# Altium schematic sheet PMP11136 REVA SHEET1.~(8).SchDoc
size 431 x 279 mm; Date: Not shown in title block; ApprovedBy: Not shown in title block; CheckedBy: Not shown in title block; Author: Not shown in title block; CompanyName: Not shown in title block; Engineer: Not shown in title block; Organization: Not shown in title block; Address1: Not shown in title block; Address2: Not shown in title block; Address3: Not shown in title block; Address4: Not shown in title block; DocumentNumber: 1; Revision: Use project parameter SCH_Rev; SheetNumber: 1; SheetTotal: 3; PageSetup: Record=PageOptions¦CenterHorizontal=True¦CenterVertical=True¦PrintScale=1.00¦XCorrection=1.00¦YCorrection=1.00¦PrintKind=0¦BorderSize=5000000¦LeftOffset=0¦BottomOffset=0¦Orientation=2¦PaperLength=1000¦PaperWidth=1000¦Scale=100¦PaperSource=15¦PrintQuality=600¦MediaType=1¦DitherType=10¦PaperKind=Letter¦PrintScaleMode=1
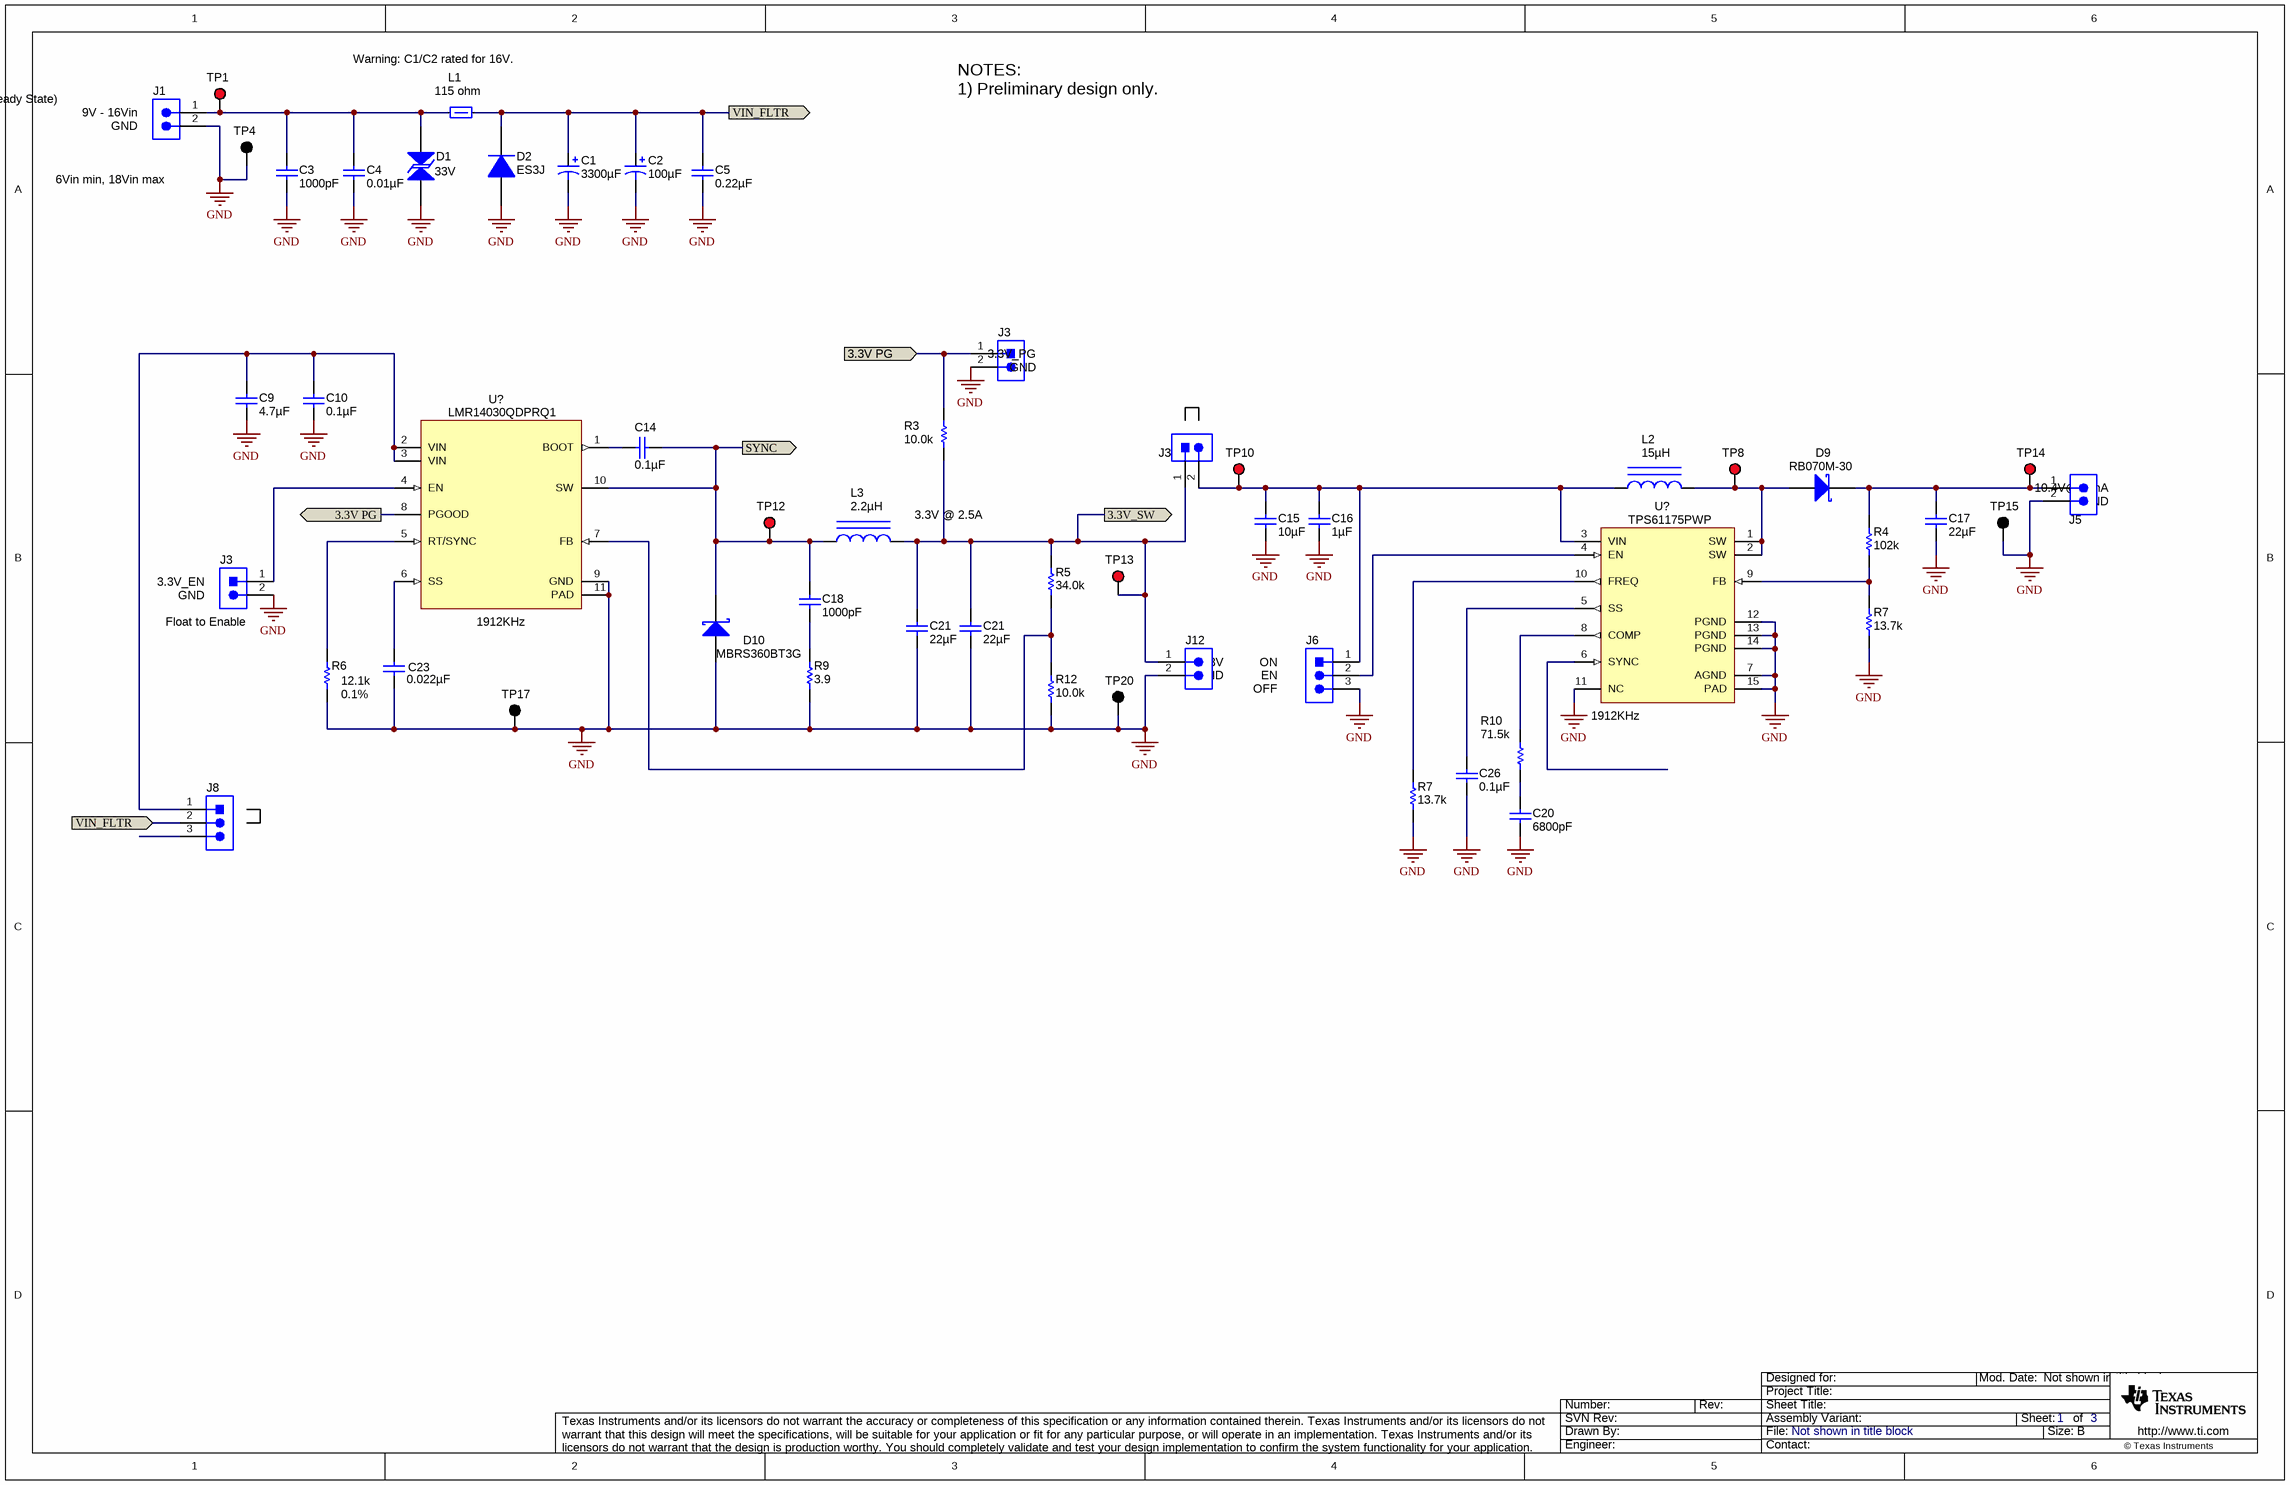
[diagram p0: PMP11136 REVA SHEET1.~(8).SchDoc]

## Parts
(Parts that share a designator on the sheet are numbered #1, #2 ... from top to bottom, then left to right.)
C1  ValueDisplayed: 3300µF  [SM_RADIAL_J16]  (hidden comment: EEV-FK1C332M)
C2  ValueDisplayed: 100µF  [SM_RADIAL_D]  (hidden comment: EEE-FK1C101P)
C3  ValueDisplayed: 1000pF  [0603]  (hidden comment: C1608C0G2A102J)
C4  ValueDisplayed: 0.01µF  [0603]  (hidden comment: C1608X7R2A103K)
C5  ValueDisplayed: 0.22µF  [0603]  (hidden comment: C1608X7R1H224K080AB)
C9  ValueDisplayed: 4.7µF  [1210]  (hidden comment: C3225X7R1H475M250AB)
C10  ValueDisplayed: 0.1µF  [0603]  (hidden comment: C1608X7R1H104K)
C14  ValueDisplayed: 0.1µF  [0603]  (hidden comment: C1608X7R1H104K)
C15  ValueDisplayed: 10µF  [0805]  (hidden comment: GRM21BR71A106KE51L)
C16  ValueDisplayed: 1µF  [0603]  (hidden comment: C1608X7R1E105K)
C17  ValueDisplayed: 22µF  [1210]  (hidden comment: C3225X7R1A226M230AC)
C18  ValueDisplayed: 1000pF  [0603]  (hidden comment: C1608C0G2A102J)
C20  ValueDisplayed: 6800pF  [0603]  (hidden comment: C1608C0G1E682J)
C21#1  ValueDisplayed: 22µF  [1210]  (hidden comment: C3225X7R1C226M250AC)
C21#2  ValueDisplayed: 22µF  [1210]  (hidden comment: C3225X7R1C226M250AC)
C23  ValueDisplayed: 0.022µF  [0603]  (hidden comment: C1608X7R1H223K)
C26  ValueDisplayed: 0.1µF  [0603]  (hidden comment: C1608X7R1H104K)
D1  value 33V  [DO-214AB-Bi]  (hidden comment: 1.5SMC33CA-E3/57T)
D2  ES3J  [SMC]
D9  RB070M-30  [SOD-123]
D10  MBRS360BT3G  [SMB]
J1  ED555/2DS  [TERM_BLK_ED555-2DS]  (value not drawn)
J3#1  PEC02SAAN  [CONN_PEC02SAAN]  (value not drawn)
J3#2  PEC02SAAN  [CONN_PEC02SAAN]  (value not drawn)
J3#3  PEC02SAAN  [CONN_PEC02SAAN]  (value not drawn)
J5  ED555/2DS  [TERM_BLK_ED555-2DS]  (value not drawn)
J6  PEC03SAAN  [CONN_PEC03SAAN]  (value not drawn)
J8  PEC03SAAN  [CONN_PEC03SAAN]  (value not drawn)
J12  ED555/2DS  [TERM_BLK_ED555-2DS]  (value not drawn)
L1  value 115 ohm  [28F0181]  (hidden comment: 28F0181-1SR-10)
L2  ValueDisplayed: 15µH  [IND_VLF403215]  (hidden comment: VLF403215MT- 150M)
L3  ValueDisplayed: 2.2µH  [SDR7045]  (hidden comment: SLF6045T-2R2N3R3-3PF)
R3  ValueDisplayed: 10.0k  [0603]  (hidden comment: CRCW060310K0FKEA)
R4  ValueDisplayed: 102k  [0603]  (hidden comment: CRCW0603102KFKEA)
R5  ValueDisplayed: 34.0k  [0603]  (hidden comment: CRCW060334K0FKEA)
R6  Value1: 0.1%  ValueDisplayed: 12.1k  [0603]
R7#1  ValueDisplayed: 13.7k  [0603]  (hidden comment: CRCW060313K7FKEA)
R7#2  ValueDisplayed: 13.7k  [0603]  (hidden comment: CRCW060313K7FKEA)
R9  value 3.9  [2010]  (hidden comment: CRCW20103R90JNEF)
R10  ValueDisplayed: 71.5k  [0603]  (hidden comment: CRCW060371K5FKEA)
R12  ValueDisplayed: 10.0k  [0603]  (hidden comment: CRCW060310K0FKEA)
TP1  5000  [Keystone5000]  (value not drawn)
TP4  5001  [Keystone5001]  (value not drawn)
TP8  5000  [Keystone5000]  (value not drawn)
TP10  5000  [Keystone5000]  (value not drawn)
TP12  5000  [Keystone5000]  (value not drawn)
TP13  5000  [Keystone5000]  (value not drawn)
TP14  5000  [Keystone5000]  (value not drawn)
TP15  5001  [Keystone5001]  (value not drawn)
TP17  5001  [Keystone5001]  (value not drawn)
TP20  5001  [Keystone5001]  (value not drawn)
U?#1  LMR14030QDPRQ1  [DPR0010A]
U?#2  TPS61175PWP  [PWP0014E_N]

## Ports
3.3V PG, 3.3V_SW, SYNC, VIN_FLTR

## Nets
GND: C1.2(-) C2.2(-) C3.2 C4.2 C5.2 C9.1 C10.2 C15.2 C16.2 C17.2 C20.2 C21#1.2 C21#2.2 C23.2 C26.2 D1.1 D2.2(A) D10.2(A) J1.2 J3#1.2 J3#3.2 J5.2 J6.3 J12.2 R6.1 R7#1.1 R7#2.1 R9.1 R12.1 TP4.1 TP15.1 TP17.1 TP20.1 U?#1.9(GND) U?#1.11(PAD) U?#2.7(AGND) U?#2.11(NC) U?#2.12(PGND) U?#2.13(PGND) U?#2.14(PGND) U?#2.15(PAD)
3.3V PG: J3#1.1 R3.2 U?#1.8(PGOOD) ; port 3.3V PG
3.3V_SW: C21#1.1 C21#2.1 J3#2.1 J12.1 L3.2 R3.1 R5.2 TP13.1 ; port 3.3V_SW
SYNC: C14.2 C18.1 D10.1(K) L3.1 TP12.1 U?#1.10(SW) ; port SYNC
VIN_FLTR: C1.1(+) C2.1(+) C5.1 D2.1(K) J8.2 L1.2 ; port VIN_FLTR
NetC3_1: C3.1 C4.1 D1.2 J1.1 L1.1 TP1.1
NetC9_2: C9.2 C10.1 J8.1 U?#1.2(VIN) U?#1.3(VIN)
NetC14_1: C14.1 U?#1.1(BOOT)
NetC15_1: C15.1 C16.1 J3#2.2 J6.1 L2.1 TP10.1 U?#2.3(VIN)
NetC17_1: C17.1 D9.1(K) J5.1 R4.2 TP14.1
NetC18_2: C18.2 R9.2
NetC20_1: C20.1 R10.1
NetC23_1: C23.1 U?#1.6(SS)
NetC26_1: C26.1 U?#2.5(SS)
NetD9_2: D9.2(A) L2.2 TP8.1 U?#2.1(SW) U?#2.2(SW)
NetJ3#3_1: J3#3.1 U?#1.4(EN)
NetJ6_2: J6.2 U?#2.4(EN)
NetR4_1: R4.1 R7#1.2 U?#2.9(FB)
NetR5_1: R5.1 R12.2 U?#1.7(FB)
NetR6_2: R6.2 U?#1.5(RT/SYNC)
NetR7#2_2: R7#2.2 U?#2.10(FREQ)
NetR10_2: R10.2 U?#2.8(COMP)

Not connected (* = marked no-connect by the designer): J8 3; U?#2 6(SYNC)

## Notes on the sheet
- (near J1) (Steady State)
- Warning: C1/C2 rated for 16V.
- (near J1) 9V - 16Vin
- (near J1) GND
- NOTES:
  1) Preliminary design only.
- (near J1) 6Vin min, 18Vin max
- (near J3#1) 3.3V_PG
- (near J3#1) GND
- (near J5) 10.4V@30mA
- (near J5) GND
- 3.3V @ 2.5A
- (near J3#3) 3.3V_EN
- (near J3#3) GND
- (near J3#3) Float to Enable
- (near U?#1) 1912KHz
- (near J12) 3.3V
- (near J12) GND
- (near J6) ON
- (near J6) EN
- (near J6) OFF
- (near U?#2) 1912KHz

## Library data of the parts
C1 = EEV-FK1C332M: CAP, AL, 3300 µF, 16 V, +/- 20%, 0.035 ohm, SMD; Manufacturer: Panasonic; Polarized: Y; CompType: Capacitor; Value: 3300uF; U/M: EA; Cap_F: 0.0033; Tolerance_%: 20; VDC_V: 16; Value2: 16V; ESR_ohm: 0.035; IRMS_A: 1.8; TaMin_C: -55; TaMax_C: 105; Cap_Case: J16
C2 = EEE-FK1C101P: CAP, AL, 100 µF, 16 V, +/- 20%, 0.36 ohm, SMD; Manufacturer: Panasonic; Polarized: Y; CompType: Capacitor; Value: 100uF; U/M: EA; Cap_F: 0.0001; Tolerance_%: 20; VDC_V: 16; Value2: 16V; ESR_ohm: 0.36; IRMS_A: 0.24; TaMin_C: -55; TaMax_C: 105; Cap_Case: D
C3 C18 = C1608C0G2A102J: CAP, CERM, 1000 pF, 100 V, +/- 5%, C0G/NP0, 0603; Manufacturer: TDK; Polarized: N; CompType: Capacitor; Value: 1000pF; U/M: EA; Cap_F: 0.000000001; Tolerance_%: 5; ESR_ohm: 0.0589; Value1: 0.0589 ohm; VDC_V: 100; Value2: 100V; TaMin_C: -55; TaMax_C: 125
C4 = C1608X7R2A103K: CAP, CERM, 0.01 µF, 100 V, +/- 10%, X7R, 0603; Manufacturer: TDK; Polarized: N; CompType: Capacitor; Value: 0.01uF; U/M: EA; Cap_F: 0.00000001; Tolerance_%: 10; ESR_ohm: 0.0661; Value1: 0.0661 ohm; VDC_V: 100; Value2: 100V; TaMin_C: -55; TaMax_C: 125
C5 = C1608X7R1H224K080AB: CAP, CERM, 0.22 µF, 50 V, +/- 10%, X7R, 0603; Manufacturer: TDK; Polarized: N; CompType: Capacitor; Value: 0.22uF; U/M: EA; Cap_F: 0.00000022; Tolerance_%: 10; Value1: Unknown; VDC_V: 50; Value2: 50V; TaMin_C: -55; TaMax_C: 125
C9 = C3225X7R1E106M: CAP, CERM, 4.7uF, 50V, +/-20%, X7R, 1210; Manufacturer: TDK; Polarized: N; CompType: Capacitor; U/M: EA; Cap_F: 0.00001; Tolerance_%: 20; ESR_Ohm: 0.0027; Value1: 0.0027 ohm; VDC_V: 50; IRMS_A: 3; TaMin_C: -55; TaMax_C: 125
C10 C14 C26 = C1608X7R1H104K: CAP, CERM, 0.1uF, 50V, +/-10%, X7R, 0603; Manufacturer: TDK; Polarized: N; CompType: Capacitor; U/M: EA; Cap_F: 0.0000001; Tolerance_%: 10; ESR_Ohm: 0.017; Value1: 0.017 ohm; VDC_V: 50; TaMin_C: -55; TaMax_C: 125
C15 = GRM21BR71A106KE51L: CAP, CERM, 10uF, 10V, +/-10%, X7R, 0805; Manufacturer: MuRata; Polarized: N; CompType: Capacitor; U/M: EA; Cap_F: 0.00001; Tolerance_%: 10; ESR_Ohm: 0.003; Value1: 0.003 ohm; TaMin_C: -55; TaMax_C: 125
C16 = C1608X7R1C105K: CAP, CERM, 1uF, 25V, +/-10%, X7R, 0603; Manufacturer: TDK; Polarized: N; CompType: Capacitor; U/M: EA; Cap_F: 0.000001; Tolerance_%: 10; ESR_Ohm: 0.0057; Value1: 0.0057 ohm; VDC_V: 25; TaMin_C: -55; TaMax_C: 125
C17 C21#1 C21#2 = C3225X7R1C226M: CAP, CERM, 22 µF, 16 V, +/- 20%, X7R, 1210; Manufacturer: TDK; Polarized: N; CompType: Capacitor; Value: 22uF; U/M: EA; Cap_F: 0.000022; Tolerance_%: 20; ESR_ohm: 0.002; Value1: 0.002 ohm; VDC_V: 16; Value2: 16V; IRMS_A: 8.11; TaMin_C: -55; TaMax_C: 125
C20 = C1608C0G1E682J: CAP, CERM, 6800 pF, 25 V, +/- 5%, C0G/NP0, 0603; Manufacturer: TDK; Polarized: N; CompType: Capacitor; Value: 6800pF; U/M: EA; Cap_F: 0.0000000068; Tolerance_%: 5; Value1: Unknown; VDC_V: 25; Value2: 25V; TaMin_C: -55; TaMax_C: 125
C23 = C1608X7R1H223K: CAP, CERM, 0.022 µF, 50 V, +/- 10%, X7R, 0603; Manufacturer: TDK; Polarized: N; CompType: Capacitor; Value: 0.022uF; U/M: EA; Cap_F: 0.000000022; Tolerance_%: 10; ESR_ohm: 0.0383; Value1: 0.0383 ohm; VDC_V: 50; Value2: 50V; TaMin_C: -55; TaMax_C: 125
D1 = 1.5SMC33CA-E3/57T: Diode, TVS, Bi, 33V, 1500W, DO-214AB; Manufacturer: Vishay-Dale; U/M: EA; Power_W: 1500; Vr_V: 28.2; RJA_CperW: 75
D2 = ES3D-E3/57T: Diode, Ultrafast, 600V, 3A, SMC; Manufacturer: Fairchild; U/M: EA; Vf_V: 0.9; Value2: 0.9V; Io_A: 3; Vr_V: 600; TJmax_C: 150
D9 = B130LAW-7-F: Diode, Schottky, 30V, 1.5A, SOD-123; Manufacturer: Rohm; U/M: EA; Vf_V: 0.38; Value1: 1A; Value2: 0.38V; Io_A: 1.5; Vr_V: 30; TJmax_C: 125
D10 = MBRS260T3G: Diode, Schottky, 60V, 3A, SMB; Manufacturer: ON Semiconductor; U/M: EA; Vf_V: 0.63; Value2: 0.63V; Io_A: 2; Vr_V: 60; TJmax_C: 125; RJC_CperW: 24
J1 J5 J12 = ED555/2DS: Terminal Block, 6A, 3.5mm Pitch, 2-Pos, TH; Manufacturer: On-Shore Technology, Inc.; SymbolCreator: a0412235; CompType: Connector; U/M: EA
J3#1-J3#3 = PEC02SAAN: Header, 100mil, 2x1, Tin, TH; Manufacturer: Sullins Connector Solutions; SymbolCreator: a0412235; U/M: EA
J6 J8 = PEC03SAAN: Header, 100mil, 3x1, Tin, TH; Manufacturer: Sullins Connector Solutions; SymbolCreator: a0799628; U/M: EA
L1 = 28F0181-1SR-10: Ferrite Bead, 115 ohm @ 100MHz, 10A, SMD, 2-Leads, Body 8.74x4.65mm; Manufacturer: Laird-Signal Integrity Products; Imax_A: 10; DCR_ohm: 0.001; Value1: 0.001 ohm; ZTyp@100MHz_Ohm: 115
L2 = VLF403215MT- 150M: Inductor, Shielded, Ferrite, 15uH, 0.87A, 0.22 ohm, SMD; Manufacturer: TDK; Ind_H: 15.0E-6; Imax_A: 0.87; Irms: 0.87A @ 40C rise; Isat: 1.19A @ 30% inductance drop; DCR_ohm: 0.22
L3 = SDR7045-2R2M: Inductor, SMT, 3.3A, 18 milliohm; Manufacturer: TDK; Value: 2.2uH; Ind_H: 2.2E-6; Imax_A: 3.3; DCR_ohm: 0.032; Material: Ferrite
R3 R12 = CRCW060310K0FKEA: RES, 10.0 k, 1%, 0.1 W, 0603; Manufacturer: Vishay-Dale; CompType: Resistor; Value: 10.0k; Res_ohm: 10000; Value_Code: 10k0; Tolerance_%: 1; Power_W: 0.1; Value2: 0.1W; VDC_V: 75; TempCo: 100 ppm/C; EIA_Code: E96; U/M: EA
R4 = CRCW0603102KFKEA: RES, 102 k, 1%, 0.1 W, 0603; Manufacturer: Vishay-Dale; CompType: Resistor; Value: 102k; Res_ohm: 102000; Tolerance_%: 1; Power_W: 0.1; Value2: 0.1W; VDC_V: 75; TempCo: 100 ppm/C; EIA_Code: E96; U/M: EA
R5 = CRCW060334K0FKEA: RES, 34.0 k, 1%, 0.1 W, 0603; Manufacturer: Vishay-Dale; CompType: Resistor; Value: 34.0k; Res_ohm: 34000; Value_Code: 34k0; Tolerance_%: 1; Power_W: 0.1; Value2: 0.1W; VDC_V: 75; TempCo: 100 ppm/C; EIA_Code: E96; U/M: EA
R6 = CRCW060312K1FKEA: RES, 12.1 k, 0.1%, 0.1 W, 0603; Manufacturer: Vishay-Dale; CompType: Resistor; Value: 12.1k; Res_ohm: 12100; Value_Code: 12k1; Tolerance_%: 1; Power_W: 0.1; Value2: 0.1W; VDC_V: 75; TempCo: 100 ppm/C; EIA_Code: E96; U/M: EA
R7#1 R7#2 = CRCW060313K7FKEA: RES, 13.7 k, 1%, 0.1 W, 0603; Manufacturer: Vishay-Dale; CompType: Resistor; Value: 13.7k; Res_ohm: 13700; Value_Code: 13k7; Tolerance_%: 1; Power_W: 0.1; Value2: 0.1W; VDC_V: 75; TempCo: 100 ppm/C; EIA_Code: E96; U/M: EA
R9 = CRCW20102R70JNEF: RES, 3.9 ohm, 5%, 0.75W, 2010; Manufacturer: Vishay-Dale; CompType: Resistor; Value_Code: 3R90; Tolerance_%: 5; Power_W: 0.75; VDC_V: 400; TempCo: 200 ppm/C; EIA_Code: E24; U/M: EA
R10 = CRCW060371K5FKEA: RES, 71.5 k, 1%, 0.1 W, 0603; Manufacturer: Vishay-Dale; CompType: Resistor; Value: 71.5k; Res_ohm: 71500; Value_Code: 71k5; Tolerance_%: 1; Power_W: 0.1; Value2: 0.1W; VDC_V: 75; TempCo: 100 ppm/C; EIA_Code: E96; U/M: EA
TP1 TP8 TP10 TP12-TP14 = 5000: Test Point, TH, Miniature, Red; Manufacturer: Keystone; CompType: Test Point Loop; U/M: EA
TP4 TP15 TP17 TP20 = 5001: Test Point, TH, Miniature, Black; Manufacturer: Keystone; CompType: Test Point Loop; U/M: EA
U?#1 = LMR14030QDPRQ1: 40V 3.5A SIMPLE SWITCHER® , 2.2MHz Step-Down Regulator with 40μA Quiescent Current, DPR0010A; Manufacturer: Texas Instruments; SymbolCreator: Altium; CompType: IC; U/M: EA
U?#2 = TPS61175PWP: 3-A High Voltage Boost Converter with Soft-start and Programmable Switching Frequency, PWP0014E; Manufacturer: Texas Instruments; SymbolCreator: a0411947; CompType: IC; U/M: EA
